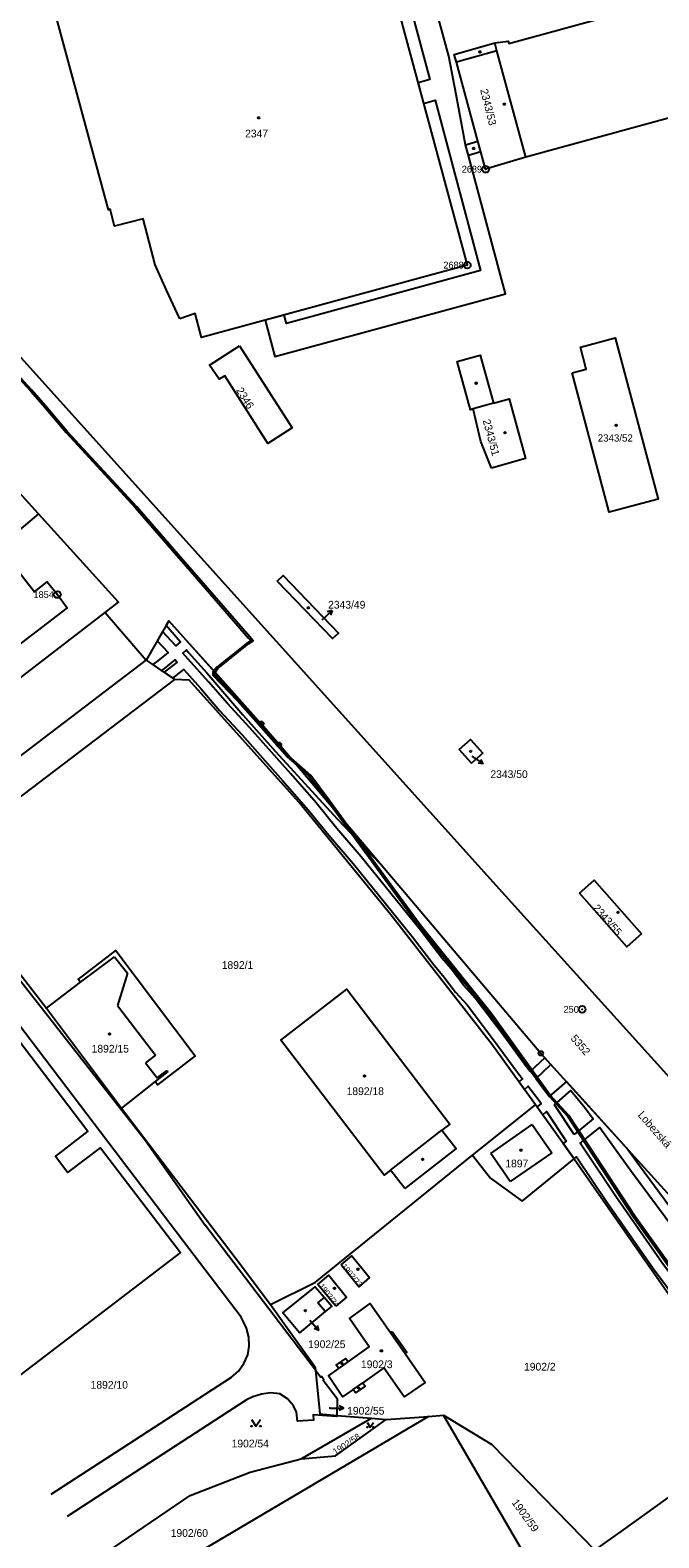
# Model space of a CAD drawing. Extents: x -821458 to -820266, y -1071458 to -1069826.
# Drawn here: x -821089.7 to -820951.1, y -1070882.8 to -1070550.7 of the extents above; entities that cross this region are included whole.
import ezdxf

# ---------------------------------------------------------------- set-up
doc = ezdxf.new("R2010")
doc.units = 0
for name, color, linetype in [('Vrstva 1', 7, 'Continuous'), ('Vrstva 13', 7, 'Continuous'), ('Vrstva 2', 7, 'Continuous'), ('Vrstva 3', 7, 'Continuous'), ('Vrstva 4', 7, 'Continuous'), ('Vrstva 5', 7, 'Continuous'), ('Vrstva 7', 7, 'Continuous'), ('Vrstva 8', 7, 'Continuous')]:
    doc.layers.add(name, color=color, linetype=linetype)

msp = doc.modelspace()

# ---------------------------------------------------------------- linework, layer by layer
at = {"layer": 'Vrstva 1'}
for p, q in [((-821087.86, -1070657.25), (-821107.02, -1070636.14)), ((-821087.86, -1070657.25), (-821096.5, -1070664.5)), ((-821101.22, -1070700.45), (-821073.15, -1070678.97)), ((-821073.15, -1070678.97), (-821064.12, -1070689.43)), ((-821111.85, -1070725.85), (-821064.12, -1070689.43)), ((-821064.12, -1070689.43), (-821057.85, -1070693.73)), ((-821091.35, -1070759.29), (-821086.06, -1070766.13)), ((-821086.06, -1070766.13), (-821069.51, -1070788.1)), ((-820992.18, -1070798.5), (-820978.27, -1070787.36)), ((-820969.81, -1070799.27), (-820978.27, -1070787.36)), ((-820969.81, -1070799.27), (-820928.15, -1070858.94)), ((-821001.88, -1070856.01), (-821068.99, -1070895.63)), ((-821029.97, -1070865.34), (-821014.46, -1070856.42)), ((-821022.12, -1070855.78), (-821014.46, -1070856.42)), ((-821014.46, -1070856.42), (-821011.19, -1070856.7)), ((-821011.19, -1070856.7), (-821001.88, -1070856.01)), ((-821001.88, -1070856.01), (-820998.58, -1070855.76))]:
    msp.add_line(p, q, dxfattribs=at)
for points in [[(-821056.67, -1070614.26), (-821059.61, -1070607.98), (-821062.15, -1070602.39), (-821064.73, -1070592.29), (-821071.06, -1070593.87), (-821072.04, -1070590.14), (-821072.37, -1070590.25), (-821084.37, -1070546.1), (-821013.78, -1070526.79), (-820993.35, -1070602.46), (-821051.9, -1070618.43), (-821053.31, -1070613.12), (-821056.67, -1070614.26)], [(-820987.3, -1070553.53), (-820984.32, -1070553.15), (-820984.15, -1070553.64), (-820896.5, -1070529.65), (-820896.17, -1070530.88), (-820896.75, -1070531.03), (-820895.04, -1070537.38), (-820894.46, -1070537.22), (-820894.09, -1070538.61), (-820894.67, -1070538.77), (-820892.95, -1070545.12), (-820892.38, -1070544.96), (-820892, -1070546.35), (-820892.58, -1070546.51), (-820890.86, -1070552.89), (-820890.28, -1070552.73), (-820889.96, -1070553.93), (-820980.44, -1070578.68)], [(-820980.44, -1070578.68), (-820989.3, -1070581.34), (-820990.35, -1070577.5), (-820993.07, -1070578.31), (-820993.71, -1070575.96), (-820991.01, -1070575.17), (-820995.75, -1070557.79), (-820996.23, -1070556.06), (-820987.3, -1070553.53)], [(-820980.44, -1070578.68), (-820986.82, -1070555.27), (-820987.3, -1070553.53)], [(-821122.14, -1070589.18), (-821105.63, -1070607.47), (-821052.06, -1070666.88), (-820984.98, -1070741.28), (-820930.99, -1070801.01), (-820892.18, -1070857.22), (-820885.9, -1070866.32)], [(-820970.22, -1070626.22), (-820967.13, -1070625.39), (-820968.39, -1070620.55), (-820960.76, -1070618.51), (-820951.27, -1070654.01), (-820962.04, -1070656.89), (-820970.22, -1070626.22)], [(-821043.56, -1070620.23), (-821031.9, -1070638.3), (-821037.27, -1070641.76), (-821046.8, -1070626.82), (-821048, -1070627.58), (-821050.13, -1070624.48), (-821043.56, -1070620.23)], [(-820987.98, -1070647.18), (-820990.37, -1070641.34), (-820992.01, -1070634.12), (-820992.65, -1070634.3), (-820995.59, -1070623.7), (-820990.49, -1070622.29), (-820987.55, -1070632.89), (-820984.1, -1070631.93), (-820980.49, -1070645.05), (-820987.98, -1070647.18)], [(-821073.15, -1070678.97), (-821070.2, -1070676.72), (-821087.86, -1070657.25)], [(-821096.5, -1070664.5), (-821088.68, -1070674.4), (-821085.91, -1070672.24), (-821083.67, -1070675.02), (-821081.48, -1070677.91), (-821095.99, -1070689.02), (-821101.01, -1070682.58), (-821104.22, -1070678.46), (-821101.77, -1070676.58), (-821105.64, -1070671.57)], [(-821035.22, -1070672.06), (-821033.94, -1070670.82), (-821021.7, -1070683.49), (-821023.01, -1070684.7), (-821035.22, -1070672.06)], [(-820830.48, -1070974.59), (-820860.94, -1070928.75), (-820897.16, -1070874.24), (-820903.48, -1070864.73), (-820933.76, -1070827.81), (-820944.98, -1070811.53), (-820977.14, -1070776.05), (-821034.82, -1070708.07), (-821038.73, -1070703.46), (-821059.1, -1070680.77), (-821064.12, -1070689.43)], [(-821057.85, -1070693.73), (-821110.68, -1070733.79), (-821091.35, -1070759.29)], [(-820978.27, -1070787.36), (-820987.76, -1070774.23), (-821010.22, -1070745.58), (-821030.47, -1070720.71), (-821054.61, -1070693.9), (-821057.85, -1070693.73)], [(-820995.14, -1070709.14), (-820992.65, -1070706.94), (-820989.94, -1070709.94), (-820992.39, -1070712.15), (-820995.14, -1070709.14)], [(-820968.62, -1070740.76), (-820965.4, -1070737.91), (-820954.94, -1070749.71), (-820958.16, -1070752.56), (-820968.62, -1070740.76)], [(-821086.06, -1070766.13), (-821078.6, -1070760.41), (-821079.07, -1070759.77), (-821070.8, -1070753.42), (-821053.28, -1070776.63), (-821061.62, -1070782.95), (-821062.15, -1070782.22), (-821069.51, -1070788.1)], [(-821007.11, -1070805.82), (-821010.24, -1070801.79), (-821011.66, -1070802.9), (-821034.41, -1070773.15), (-821019.91, -1070761.91), (-820997.19, -1070791.62), (-820998.92, -1070792.97), (-820995.79, -1070796.99), (-821007.11, -1070805.82)], [(-821085.02, -1070873.12), (-821066.67, -1070861.23), (-821045.28, -1070847.39), (-821043.79, -1070846.02), (-821042.61, -1070844.38), (-821041.71, -1070842.48), (-821041.39, -1070840.53), (-821041.49, -1070838.54), (-821041.98, -1070836.55), (-821042.62, -1070835.15), (-821043.18, -1070834.17), (-821055.9, -1070817.47), (-821096.91, -1070763.55)], [(-821137.57, -1070799.4), (-821096.27, -1070767.81), (-821077.16, -1070792.93), (-821076.94, -1070793.21), (-821084.09, -1070798.68), (-821081.35, -1070802.28), (-821074.19, -1070796.85), (-821056.57, -1070819.88), (-821099.56, -1070852.72)], [(-821069.51, -1070788.1), (-821044.29, -1070821.28), (-821036.72, -1070831.36)], [(-821036.72, -1070831.36), (-821026.76, -1070826.48), (-820992.18, -1070798.5)], [(-820992.18, -1070798.5), (-820988.22, -1070803.56), (-820981.24, -1070808.59), (-820969.81, -1070799.27)], [(-821021.16, -1070822.64), (-821018.79, -1070820.63), (-821014.85, -1070825.45), (-821017.2, -1070827.47), (-821021.16, -1070822.64)], [(-821022.3, -1070831.76), (-821026.25, -1070826.94), (-821023.87, -1070824.93), (-821019.93, -1070829.77), (-821022.3, -1070831.76)], [(-821024.67, -1070832.92), (-821030.3, -1070837.57), (-821033.95, -1070833.19), (-821026.83, -1070827.44), (-821024.81, -1070829.82), (-821023.21, -1070831.71), (-821024.67, -1070832.92)], [(-821036.72, -1070831.36), (-821026.9, -1070845), (-821026.82, -1070845.79)], [(-821009.88, -1070837.28), (-821006.68, -1070841.87), (-821007.05, -1070842.13), (-821002.6, -1070848.51), (-821007.27, -1070851.71), (-821011.7, -1070845.33), (-821016.37, -1070848.61), (-821015.85, -1070849.35), (-821017.98, -1070850.81), (-821018.48, -1070850.09), (-821020.8, -1070851.72), (-821023.93, -1070847.09), (-821021.63, -1070845.49), (-821022.21, -1070844.71), (-821020.07, -1070843.27), (-821019.56, -1070843.99), (-821014.94, -1070840.72), (-821019.29, -1070834.41), (-821014.71, -1070831.17), (-821010.26, -1070837.54), (-821009.88, -1070837.28)], [(-821026.82, -1070845.79), (-821025.61, -1070847.38), (-821025.4, -1070847.25), (-821024.94, -1070847.87), (-821025.12, -1070848.02), (-821022.01, -1070852.09), (-821022.12, -1070855.78)], [(-821026.82, -1070845.79), (-821025.85, -1070855.47), (-821022.12, -1070855.78)], [(-821022.12, -1070855.78), (-821022.13, -1070856.02), (-821027.28, -1070855.63), (-821027.21, -1070856.81), (-821030.78, -1070857.06), (-821030.98, -1070855.04), (-821031.64, -1070853.65), (-821032.95, -1070852.11), (-821034.66, -1070851.02), (-821036.67, -1070850.85), (-821038.67, -1070851.12), (-821040.59, -1070851.68), (-821041.96, -1070852.36), (-821063.36, -1070866.22), (-821081.54, -1070878.02)], [(-821029.97, -1070865.34), (-821022.4, -1070864.66), (-821011.19, -1070856.7)], [(-820965.26, -1070885.48), (-820977.22, -1070892.46), (-820998.58, -1070855.76)], [(-820998.58, -1070855.76), (-820987.94, -1070862.19), (-820965.26, -1070885.48)], [(-820965.26, -1070885.48), (-820958.9, -1070880.99), (-820937.72, -1070865.8), (-820928.15, -1070858.94)], [(-821074.87, -1070887.37), (-821054.43, -1070873.41), (-821041.17, -1070868.25), (-821029.97, -1070865.34)]]:
    msp.add_lwpolyline(points, dxfattribs=at)
at = {"layer": 'Vrstva 13'}
for points in [[(-821011.58, -1070524.4), (-821001.61, -1070561.6), (-821004.19, -1070562.3), (-821002.97, -1070566.84), (-821000.42, -1070566.15), (-820990.44, -1070603.64), (-821033.17, -1070615.29), (-821033.67, -1070613.46), (-821037.91, -1070614.61), (-821035.73, -1070622.62), (-820984.92, -1070608.78), (-820993.07, -1070578.31), (-820993.71, -1070575.96), (-820995.81, -1070564.9), (-820997.43, -1070556.41), (-821006.07, -1070524.66)], [(-821100.86, -1070618.05), (-821089.54, -1070630.22), (-821086.54, -1070633.66), (-821081.75, -1070639.32), (-821066.44, -1070655.91), (-821057.31, -1070666.41), (-821055.27, -1070668.77), (-821041.53, -1070684.59), (-821041.06, -1070685.12), (-821041.71, -1070685.54), (-821048.52, -1070691.03), (-821049.18, -1070691.82), (-821048.92, -1070692.11), (-821048.28, -1070691.29), (-821041.51, -1070685.82), (-821040.54, -1070685.2), (-821041.26, -1070684.36), (-821055.01, -1070668.54), (-821057.05, -1070666.18), (-821066.18, -1070655.67), (-821081.49, -1070639.08), (-821086.28, -1070633.44), (-821089.28, -1070629.98), (-821100.6, -1070617.81)], [(-820944.42, -1070815.67), (-820955.42, -1070800.84), (-820958.36, -1070796.76), (-820971.49, -1070782.28), (-820975.26, -1070785.57), (-820978.24, -1070781.67), (-820974.9, -1070778.52), (-820976.27, -1070777.01), (-820979.49, -1070780.04), (-820980.13, -1070779.22), (-820985.89, -1070771.39), (-820991.61, -1070763.92), (-820994.13, -1070761.11), (-820996.91, -1070757.43), (-820998.87, -1070755.19), (-821003.64, -1070748.9), (-821016.72, -1070732.75), (-821022.08, -1070726.55), (-821026.62, -1070720.91), (-821032.22, -1070714.48), (-821041.26, -1070704.34), (-821046.21, -1070699.04), (-821050.39, -1070694.22), (-821054.81, -1070689.25), (-821056.04, -1070687.94), (-821055.18, -1070687.21), (-821054.82, -1070687.73), (-821050.75, -1070692.23), (-821042.83, -1070701.53), (-821035.6, -1070709.54), (-821022.01, -1070724.44), (-821012.57, -1070734.29), (-821019.49, -1070726.14), (-821022.53, -1070722.56), (-821031.15, -1070712.39), (-821033, -1070710.21), (-821034.82, -1070708.07), (-821038.73, -1070703.46), (-821048.92, -1070692.11), (-821049.18, -1070691.82), (-821059.1, -1070680.77), (-821059.68, -1070681.77), (-821056.54, -1070685.45), (-821057.56, -1070686.31), (-821060.49, -1070683.17), (-821061.66, -1070685.18), (-821059.26, -1070687.74), (-821061.54, -1070689.64), (-821062.64, -1070690.45), (-821060.69, -1070691.78), (-821060.17, -1070691.4), (-821057.74, -1070689.37), (-821057.27, -1070689.87), (-821060.17, -1070692.14), (-821058.25, -1070693.46), (-821055.77, -1070691.52), (-821052.06, -1070695.69)], [(-821052.06, -1070695.69), (-821047.93, -1070700.58), (-821042.96, -1070705.9), (-821033.96, -1070716), (-821028.4, -1070722.39), (-821023.86, -1070728.03), (-821018.5, -1070734.23), (-821005.46, -1070750.32), (-821000.67, -1070756.65), (-820998.71, -1070758.89), (-820995.91, -1070762.59), (-820993.39, -1070765.4), (-820987.75, -1070772.77), (-820981.97, -1070780.61), (-820981.18, -1070781.64), (-820981.91, -1070782.33), (-820980.7, -1070783.99), (-820979.94, -1070783.27), (-820977.51, -1070786.43), (-820977.05, -1070787.13), (-820977.93, -1070787.84), (-820976.7, -1070789.57), (-820975.88, -1070788.89), (-820971.56, -1070795.4), (-820972.19, -1070795.92), (-820969.81, -1070799.27), (-820969.24, -1070798.81), (-820962.49, -1070808.89), (-820952.33, -1070823.49), (-820942.57, -1070836.51)], [(-820944.15, -1070829.04), (-820956.36, -1070812.01), (-820966.39, -1070796.66), (-820969.25, -1070792.29), (-820970.93, -1070789.73), (-820975.04, -1070785.28), (-820978.88, -1070779.96), (-820988.16, -1070767.12), (-821003.75, -1070747.72), (-821019.49, -1070726.14), (-821022.53, -1070722.56), (-821004.03, -1070747.94), (-820988.44, -1070767.34), (-820979.16, -1070780.17), (-820975.32, -1070785.5), (-820971.21, -1070789.95), (-820969.55, -1070792.48), (-820966.69, -1070796.86), (-820956.64, -1070812.21), (-820944.43, -1070829.24)]]:
    msp.add_lwpolyline(points, dxfattribs=at)
for points in [[(-821049.18, -1070691.82), (-821049.43, -1070692.11), (-821049.38, -1070692.79), (-821044.07, -1070698.38), (-821032.94, -1070710.79), (-821031.15, -1070712.39), (-821033, -1070710.21), (-821043.81, -1070698.14), (-821049.04, -1070692.65), (-821049.07, -1070692.23), (-821048.92, -1070692.11)], [(-821022.53, -1070722.56), (-821019.49, -1070726.14), (-821023.74, -1070720.31), (-821027.84, -1070714.89), (-821032.7, -1070710.55), (-821031.15, -1070712.39), (-821028.1, -1070715.13)], [(-820969.75, -1070793.93), (-820974.11, -1070787.37), (-820970.53, -1070784.25), (-820967.46, -1070787.97), (-820965.56, -1070790.5)], [(-820904.89, -1070889.85), (-820906.75, -1070887.02), (-820915.84, -1070872.29), (-820921.1, -1070864.54), (-820924.16, -1070858.76), (-820935.49, -1070842.47), (-820940.7, -1070835.15), (-820950.45, -1070822.13), (-820960.57, -1070807.59), (-820967.99, -1070796.51), (-820968.45, -1070795.86), (-820964.16, -1070792.35), (-820957.12, -1070802.08), (-820946.13, -1070816.91), (-820939.51, -1070826.31), (-820927.43, -1070843.51), (-820917.95, -1070857.45), (-820910.17, -1070868.83), (-820902.77, -1070879.51), (-820898.51, -1070886.1), (-820899.32, -1070886.63)]]:
    msp.add_lwpolyline(points, close=True, dxfattribs=at)
at = {"layer": 'Vrstva 3'}
for points in [[(-821040.92, -1070856.66), (-821039.92, -1070858.16), (-821038.92, -1070856.66)], [(-821015.38, -1070857.37), (-821014.71, -1070858.38), (-821014.04, -1070857.37)]]:
    msp.add_lwpolyline(points, dxfattribs=at)
for centre, radius in [((-821040.92, -1070858.16), 0.1), ((-821038.92, -1070858.16), 0.1), ((-821015.38, -1070858.38), 0.067), ((-821014.04, -1070858.38), 0.067)]:
    msp.add_circle(centre, radius, dxfattribs=at)
at = {"layer": 'Vrstva 4'}
for p, q in [((-820986.82, -1070555.27), (-820995.75, -1070557.79)), ((-820990.35, -1070577.5), (-820991.01, -1070575.17)), ((-820987.55, -1070632.89), (-820992.01, -1070634.12)), ((-821078.6, -1070760.41), (-821071.06, -1070754.83)), ((-821071.06, -1070754.83), (-821068.19, -1070758.42)), ((-821068.19, -1070758.42), (-821070.39, -1070765.49)), ((-821092, -1070759.79), (-821064.25, -1070795.28)), ((-821070.39, -1070765.49), (-821062.05, -1070776.46)), ((-821062.05, -1070776.46), (-821064.25, -1070778.16)), ((-821064.25, -1070778.16), (-821061.67, -1070781.48)), ((-821059.3, -1070780.03), (-821062.15, -1070782.22)), ((-821061.67, -1070781.48), (-821059.47, -1070779.8)), ((-821059.47, -1070779.8), (-821059.3, -1070780.03)), ((-820988.17, -1070798.11), (-820979.01, -1070791.71)), ((-820979.01, -1070791.71), (-820974.7, -1070797.94)), ((-821064.25, -1070795.28), (-821051.12, -1070813.86)), ((-821010.24, -1070801.79), (-820998.92, -1070792.97)), ((-820983.86, -1070804.31), (-820988.17, -1070798.11)), ((-820974.7, -1070797.94), (-820983.86, -1070804.31)), ((-821026.82, -1070845.79), (-821051.12, -1070813.86)), ((-821026.3, -1070830.99), (-821024.81, -1070829.82)), ((-821024.67, -1070832.92), (-821026.3, -1070830.99)), ((-821010.26, -1070837.54), (-821007.05, -1070842.13)), ((-821021.63, -1070845.49), (-821019.56, -1070843.99)), ((-821018.48, -1070850.09), (-821016.37, -1070848.61))]:
    msp.add_line(p, q, dxfattribs=at)
at = {"layer": 'Vrstva 5'}
for centre in [(-820990.54, -1070555.5), (-820985.17, -1070567.01), (-821039.31, -1070570.03), (-820991.95, -1070576.77), (-820991.38, -1070628.47), (-820985.01, -1070639.36), (-820960.52, -1070637.74), (-821028.38, -1070677.94), (-820992.59, -1070709.54), (-820960.12, -1070744.98), (-821072.19, -1070771.77), (-821015.99, -1070781.04), (-820981.49, -1070797.38), (-821003.19, -1070799.37), (-821017.43, -1070823.59), (-821022.61, -1070827.81), (-821029.02, -1070832.73), (-821012.25, -1070841.56), (-821020.94, -1070844.4), (-821017.26, -1070849.73)]:
    msp.add_circle(centre, 0.175, dxfattribs=at)
at = {"layer": 'Vrstva 7'}
for p, q in [((-821025.3, -1070680.56), (-821023.1, -1070678.51)), ((-821023.1, -1070678.51), (-821024.18, -1070678.83)), ((-821023.1, -1070678.51), (-821023.5, -1070679.56)), ((-820992.3, -1070710.59), (-820989.84, -1070712.31)), ((-820989.84, -1070712.31), (-820990.95, -1070712.15)), ((-820989.84, -1070712.31), (-820990.38, -1070711.33)), ((-821028.03, -1070834.81), (-821026.06, -1070837.07)), ((-821026.06, -1070837.07), (-821027.1, -1070836.65)), ((-821026.06, -1070837.07), (-821026.34, -1070835.99)), ((-821023.56, -1070854.19), (-821023.76, -1070854.19)), ((-821023.56, -1070854.19), (-821020.56, -1070854.19)), ((-821020.56, -1070854.19), (-821021.56, -1070853.69)), ((-821020.56, -1070854.19), (-821021.56, -1070854.69))]:
    msp.add_line(p, q, dxfattribs=at)
at = {"layer": 'Vrstva 8'}
for centre, radius in [((-820989.3, -1070581.34), 0.75), ((-820989.3, -1070581.34), 0.03), ((-820993.35, -1070602.46), 0.75), ((-820993.35, -1070602.46), 0.03), ((-821083.67, -1070675.02), 0.75), ((-821083.67, -1070675.02), 0.03), ((-821038.73, -1070703.46), 0.5), ((-821038.73, -1070703.46), 0.0303), ((-821034.82, -1070708.07), 0.5), ((-821034.82, -1070708.07), 0.0303), ((-820968.02, -1070766.36), 0.75), ((-820968.02, -1070766.36), 0.03), ((-820977.14, -1070776.05), 0.5), ((-820977.14, -1070776.05), 0.0303)]:
    msp.add_circle(centre, radius, dxfattribs=at)

# ---------------------------------------------------------------- texts
at = {"layer": 'Vrstva 2'}
for s, height, rotation, p in [('2343/53', 1.7, 284, (-820990.5, -1070563.88)), ('2346', 1.7, 302, (-821044.35, -1070630.04)), ('2343/51', 1.7, 285, (-820989.95, -1070636.67)), ('2343/55', 1.7, 311, (-820965.78, -1070744.14)), ('5352', 1.7, 311, (-820970.68, -1070772.85)), ('1902/23', 1.2, 310, (-821021.1, -1070823.02)), ('1902/24', 1.2, 308, (-821026.06, -1070827.34)), ('1902/58', 1.403, 33, (-821022.4, -1070864.52)), ('1902/59', 1.7, 306, (-820983.64, -1070874.99))]:
    msp.add_text(s, height=height, rotation=rotation, dxfattribs=at).set_placement(p)
for s, height, p in [('2347', 1.7, (-821042.3, -1070574.33)), ('2343/52', 1.6, (-820964.59, -1070641.33)), ('2343/49', 1.7, (-821024.01, -1070678.1)), ('2343/50', 1.7, (-820988.24, -1070715.42)), ('1892/1', 1.7, (-821047.45, -1070757.45)), ('1892/15', 1.7, (-821076.12, -1070775.88)), ('1892/18', 1.7, (-821019.93, -1070785.24)), ('1897', 1.7, (-820984.95, -1070801.16)), ('1902/25', 1.7, (-821028.4, -1070840.96)), ('1902/3', 1.7, (-821016.76, -1070845.38)), ('1902/2', 1.7, (-820980.83, -1070845.91)), ('1892/10', 1.7, (-821076.34, -1070849.9)), ('1902/55', 1.7, (-821019.81, -1070855.61)), ('1902/54', 1.7, (-821045.27, -1070862.83)), ('1902/60', 1.7, (-821058.69, -1070882.54))]:
    msp.add_text(s, height=height, dxfattribs=at).set_placement(p)
at = {"layer": 'Vrstva 7'}
msp.add_text('Lobezská', height=1.7, rotation=311, dxfattribs=at).set_placement((-820955.86, -1070789.71))
at = {"layer": 'Vrstva 8'}
for s, p in [('2689', (-820994.55, -1070582.09)), ('2688', (-820998.6, -1070603.21)), ('1854', (-821088.92, -1070675.77)), ('250', (-820972.12, -1070767.11))]:
    msp.add_text(s, height=1.5, dxfattribs=at).set_placement(p)

doc.saveas('drawing.dxf')
